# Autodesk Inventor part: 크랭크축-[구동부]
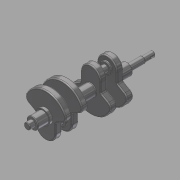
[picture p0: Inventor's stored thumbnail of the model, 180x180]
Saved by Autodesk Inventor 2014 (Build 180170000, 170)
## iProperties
Created: 2017-03
Part Number: 크랭크축-[구동부]
Material: 강철, 탄소
Document SubType Name: Modeling
Designer: mduedu
Density: 7.87 g/cm^3
Mass: 1840.77 g
Surface Area: 500.249 cm^2
Volume: 233.897 cm^3
Appearance: 반광택
Author: mduedu
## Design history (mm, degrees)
sketch "스케치1" dims "d5" = 57
  geometry: L1 (-19, 21.243)-(-19, 3.243); L2 (-19, 3.243)-(-40.023, -8.895); L3 (19, 21.243)-(19, 3.243); L4 (0, 21.243)-(0, -41); L5 (19, 3.243)-(40.023, -8.895); C1 r 6 at (0, 0); C2 r 13.5 at (0, 0); A1 r 41 centre (0, 0) between (-40.023, -8.895) and (0, -41); A2 r 41 centre (0, 0) between (0, -41) and (40.023, -8.895); A3 r 19 centre (0, 21.243) between (19, 21.243) and (0, 40.243); A4 r 19 centre (0, 21.243) between (0, 40.243) and (-19, 21.243); 3 further points
  constraints: 10 end point, 8 point on circle, 6 centre point, 5 coincident, 3 symmetric about line, 2 point on line, 1 parallel, 1 tangent, 1 vertical, 1 vertical alignment, 5 other
  dimensions: "d0" = 12 diameter of C1; "d1" = 27 diameter of C2; "d2" = 18 distance of L1.start L1.end; "d3" = 120 deg angle of L2 L1; "d4" = 41 radius of A1; "d6" = 19 radius of A4
extrude "돌출1" new body sketch "스케치1" distance "d7" = 12; taper "d8" = 0 deg
extrude "돌출2" join sketch "스케치1" distance "d9" = 5; taper "d10" = 0 deg
extrude "돌출3" join sketch "스케치1" distance "d11" = 75; taper "d12" = 0 deg
sketch "스케치2"
  geometry: C1 r 11 at (0, 21.243); C2 r 6 at (0, 21.243); A1 r 19 centre (0, 21.243) between (19, 21.243) and (-19, 21.243) reference; 1 further point
  constraints: 2 centre point, 2 coincident
  dimensions: "d13" = 22 diameter of C1; "d14" = 12 diameter of C2
extrude "돌출4" join sketch "스케치2" distance "d15" = 3; taper "d16" = 0 deg
extrude "돌출5" join sketch "스케치2" distance "d17" = 16; taper "d18" = 0 deg
fillet "모깎기1" dims "d19" = 3, "d20" = 10
fillet "모깎기2" dims "d21" = 2
sketch "스케치3"
  geometry: C1 r 11 at (0, 0); 1 further point
  constraints: 1 centre point, 1 coincident
  dimensions: "d22" = 22 diameter of C1
extrude "돌출6" join sketch "스케치3" distance "d23" = 21; taper "d24" = 0 deg
sketch "스케치4"
  geometry: C1 r 6 at (0, 0) reference; C2 r 5 at (0, 0); 1 further point
  constraints: 1 centre point
  dimensions: "d25" = 1 radial gap between concentric circles of C1 C2
extrude "돌출7" cut sketch "스케치4" distance "d26" = 20; taper "d27" = 0 deg
node "작업 평면1"
sketch "스케치5"
  geometry: L1 (-5, 0)-(5, 0) reference; L2 (-1.5, 0)-(1.5, 0); L3 (1.5, 0)-(1.5, 8.5); L4 (-1.5, 8.5)-(-1.5, 0); A1 r 1.5 centre (0, 8.5) between (1.5, 8.5) and (-1.5, 8.5); 1 further point
  constraints: 6 end point, 2 point on circle, 2 tangent, 1 centre point, 1 horizontal, 1 parallel, 1 perpendicular, 1 point on line, 1 vertical alignment
  dimensions: "d28" = 3 distance between parallel lines of L3 L4; "d30" = 10 dimension on A1 L1
extrude "돌출8" cut sketch "스케치5" distance "d31" = 1.8; taper "d32" = 0 deg
chamfer "모따기1" distance "d33" = 1; stored, may be unused: second distance "d34" = 2, angle "d35" = 45 deg
chamfer "모따기2" distance "d36" = 1; stored, may be unused: second distance "d37" = 2, angle "d38" = 45 deg
node "작업 평면2"
sketch "스케치6"
  geometry: C1 r 11 at (0, 0) reference; C2 r 11 at (0, 0) reference; 1 further point
extrude "돌출9" join sketch "스케치6" distance "d39" = 42; taper "d40" = 0 deg
sketch "스케치7" dims "d46" = 57
  geometry: L1 (-19, -21.243)-(-19, -3.243); L2 (19, -21.243)-(19, -3.243); L3 (-19, -3.243)-(-40.023, 8.895); L4 (19, -3.243)-(40.023, 8.895); L5 (0, -21.243)-(0, 41); C1 r 13.5 at (0, 0); C2 r 6 at (0, 0); A1 r 19 centre (0, -21.243) between (0, -40.243) and (19, -21.243); A2 r 19 centre (0, -21.243) between (-19, -21.243) and (0, -40.243); A3 r 41 centre (0, 0) between (0, 41) and (-40.023, 8.895); A4 r 41 centre (0, 0) between (40.023, 8.895) and (0, 41); 3 further points
  constraints: 10 end point, 8 point on circle, 6 centre point, 5 coincident, 3 symmetric about line, 2 point on line, 1 parallel, 1 tangent, 1 vertical, 5 other
  dimensions: "d41" = 12 diameter of C2; "d42" = 27 diameter of C1; "d43" = 18 distance of L2.start L2.end; "d44" = 120 deg angle of L4 L2; "d45" = 41 radius of A4; "d47" = 19 radius of A1
extrude "돌출10" join sketch "스케치7" distance "d48" = 12; taper "d49" = 0 deg
sketch "스케치8"
  geometry: C1 r 11 at (0, -21.243); C2 r 6 at (0, -21.243); A1 r 19 centre (0, -21.243) between (-19, -21.243) and (19, -21.243) reference; 1 further point
  constraints: 2 centre point, 2 coincident
  dimensions: "d50" = 22 diameter of C1; "d51" = 12 diameter of C2
extrude "돌출11" join sketch "스케치8" distance "d52" = 3; taper "d53" = 0 deg
extrude "돌출12" join sketch "스케치8" distance "d54" = 16; taper "d55" = 0 deg
fillet "모깎기3" dims "d56" = 3, "d57" = 10
fillet "모깎기4" dims "d58" = 2
chamfer "모따기3" distance "d59" = 1; stored, may be unused: second distance "d60" = 2, angle "d61" = 45 deg
node "작업 평면3"
fillet "모깎기5" dims "d62" = 1
sketch "스케치9"
  geometry: C1 r 13.5 at (0, 0) reference; 1 further point
extrude "돌출13" join sketch "스케치9" distance "d63" = 5; taper "d64" = 0 deg
sketch "스케치10"
  geometry: C1 r 6 at (0, 0) reference; 1 further point
extrude "돌출14" join sketch "스케치10" distance "d65" = 30; taper "d66" = 0 deg
sketch "스케치11"
  geometry: C1 r 11 at (0, 0); 1 further point
  constraints: 1 centre point, 1 coincident
  dimensions: "d67" = 22 diameter of C1
extrude "돌출15" join sketch "스케치11" distance "d68" = 20; taper "d69" = 0 deg
chamfer "모따기4" distance "d70" = 1; stored, may be unused: second distance "d71" = 2, angle "d72" = 45 deg
chamfer "모따기5" distance "d75" = 0.7; stored, may be unused: second distance "d76" = 2, angle "d77" = 30 deg
fillet "모깎기6" dims "d78" = 0.3
node "솔리드1"
mirror "대칭1"
mirror "대칭2"
node "투영된 루프1"
